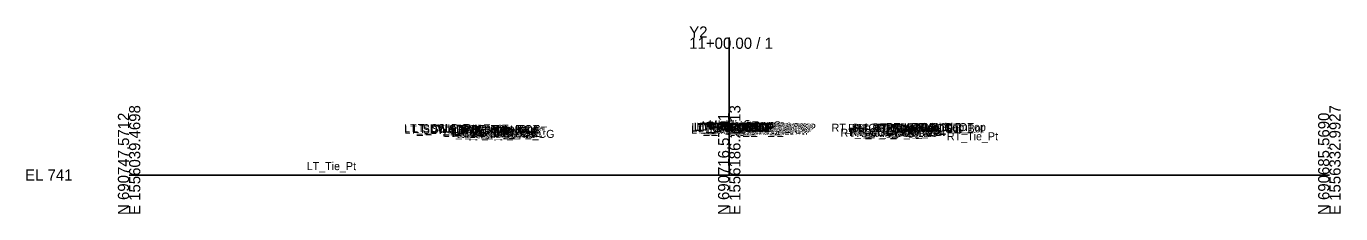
# Model space of a CAD drawing. Extents: x -26 to 4229, y -10 to 9523.
# Drawn here: x -25.7 to 302.8, y 490.3 to 537.2 of the extents above; entities that cross this region are included whole.
import ezdxf

# ---------------------------------------------------------------- set-up
doc = ezdxf.new("R2010")
doc.units = 0
doc.layers.add('Default', color=7, linetype='Continuous')
doc.layers.add('Exist Cross Section Cell', color=7, linetype='Continuous')

msp = doc.modelspace()

# ---------------------------------------------------------------- linework, layer by layer
at = {"layer": 'Exist Cross Section Cell'}
for p, q in [((150, 500), (150, 534.38)), ((0, 500), (150, 500)), ((150, 500), (300, 500))]:
    msp.add_line(p, q, dxfattribs=at)

# ---------------------------------------------------------------- texts
at = {"layer": 'Default'}
for s, height, p in [('LT_SDWK_Out_Top', 2, (68.76, 510.71)), ('LT_CSLP_Pnt', 2, (70.7, 510.74)), ('LT_Sub_Trench_Out_DLT', 2, (71.02, 510.54)), ('LT_SDWK_In_Top', 2, (75.39, 510.61)), ('LT_CG_Top_Face', 2, (80.29, 510.5)), ('LT_CG_Top_BOC', 2, (80.81, 510.5)), ('LT_PV2_OEEOP', 2, (140.56, 510.99)), ('LT_PV3_OEEOP', 2, (140.56, 510.74)), ('LT_PV1_OEEOP', 2, (141.12, 511.12)), ('LT_PV2_IEEOP', 2, (141.2, 510.99)), ('LT_PV1_IEEOP', 2, (141.77, 511.12)), ('LT_PV2_PGL1', 2, (142.13, 510.99)), ('LT_PV3_PGL1', 2, (142.13, 510.74)), ('LT_PV2_PGL', 2, (142.46, 510.99)), ('LT_PV1_PGL', 2, (143.03, 511.25)), ('MI_Face In', 2, (143.15, 511.41)), ('MI_Bot In', 2, (144.13, 511.25)), ('MI_Top In', 2, (144.86, 511.66)), ('MI_Crown', 2, (149.07, 511.74)), ('RT_PV2_OEEOP', 2, (150.01, 510.75)), ('RT_PV3_OEEOP', 2, (150.01, 510.5)), ('RT_PV1_OEEOP', 2, (150.58, 510.88)), ('RT_PV2_IEEOP', 2, (150.66, 510.75)), ('MI_Face Out', 2, (151.01, 511.17)), ('MI_Top Out', 2, (151.22, 511.42)), ('RT_PV1_IEEOP', 2, (151.22, 510.88)), ('RT_PV2_PGL1', 2, (151.58, 510.75)), ('RT_PV3_PGL1', 2, (151.58, 510.5)), ('RT_PV2_PGL', 2, (151.92, 510.75)), ('MI_Bot Out', 2, (152.01, 511)), ('RT_PV1_PGL', 2, (152.48, 511)), ('RT_Sub_Trench_Out_DLT', 2, (175.59, 510.83)), ('RT_CG_Top_Face', 2, (179.71, 510.79)), ('RT_CG_Top_BOC', 2, (181.24, 510.79)), ('RT_SDWK_In_Top', 2, (185.81, 510.9)), ('RT_SDWK_In_Bot', 2, (185.84, 510.57)), ('RT_SDWK_Out_Top', 2, (189.19, 511)), ('RT_SDWK_Out_Bot', 2, (189.22, 510.67)), ('RT_Shld_O', 2, (195.54, 510.99)), ('CSLP_Pnt', 2, (197.87, 511.03)), ('LT_SDWK_Out_Bot', 2, (68.79, 510.38)), ('LT_SDWK_In_Bot', 2, (75.42, 510.28)), ('LT_CG1_Shelf_Out', 2, (78.58, 509.48)), ('LT_CG_Bot_BOC', 2, (80.84, 509.49)), ('LT_CG_Top_Gut', 2, (81.26, 510)), ('LT_Sub_OEOP', 2, (81.88, 509.22)), ('LT_Sub_OEOT_CG', 2, (82.4, 509.29)), ('LT_CG_Bot_IE', 2, (84.94, 509.54)), ('LT_Sub_OEOT', 2, (85.11, 509.25)), ('LT_PV2_OEOT', 2, (85.2, 509.87)), ('LT_PV3_OEOT', 2, (85.2, 509.62)), ('LT_PV1_OEOT', 2, (85.77, 510.12)), ('LT_Sub_OEEOP', 2, (140.46, 510.37)), ('LT_PV4_PGL', 2, (142.46, 510.37)), ('RT_Sub_OEEOP', 2, (149.92, 510.13)), ('RT_PV4_PGL', 2, (151.92, 510.13)), ('RT_Sub_OEOT_CG', 2, (177.82, 509.58)), ('RT_CG1_Shelf_Out', 2, (180, 509.77)), ('RT_CG_Bot_IE', 2, (180.37, 509.83)), ('RT_Sub_OEOT', 2, (180.53, 509.53)), ('RT_PV2_OEOT', 2, (180.63, 510.16)), ('RT_PV3_OEOT', 2, (180.63, 509.91)), ('RT_CG_Top_Gut', 2, (180.69, 510.29)), ('RT_PV1_OEOT', 2, (181.19, 510.41)), ('RT_CG_Bot_BOC', 2, (181.27, 509.78)), ('RT_Sub_OEOP', 2, (183.82, 509.51)), ('RT_Tie_Pt', 2, (204.41, 508.69)), ('LT_Tie_Pt', 2, (44.39, 501.22)), ('-', 0.0001, (0, 500)), ('-', 0.0001, (0, 500)), ('-', 0.0001, (0, 500)), ('-', 0.0001, (0, 500)), ('-', 0.0001, (0, 500)), ('-', 0.0001, (0, 500)), ('-', 0.0001, (0, 500)), ('-', 0.0001, (0, 500)), ('-', 0.0001, (0, 500))]:
    msp.add_text(s, height=height, dxfattribs=at).set_placement(p)
at = {"layer": 'Exist Cross Section Cell'}
for s, p in [('Y2', (140, 534.38)), ('11+00.00 / 1', (140, 531.58)), ('EL 741', (-26, 498.6))]:
    msp.add_text(s, height=2.8, dxfattribs=at).set_placement(p)
for s, p in [('E 1556039.4698', (2.8, 490)), ('E 1556186.2313', (152.8, 490)), ('E 1556332.9927', (302.8, 490)), ('N 690747.5712', (0, 490)), ('N 690716.5701', (150, 490)), ('N 690685.5690', (300, 490))]:
    msp.add_text(s, height=2.8, rotation=90, dxfattribs=at).set_placement(p)

doc.saveas('drawing.dxf')
